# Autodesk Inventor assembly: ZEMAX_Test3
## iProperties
Created: 2005-04
Part Number: ZEMAX_Test3
Document SubType Name: Assembly
Designer: Nordmeyer
Manufacturer: Standard
Standards Organization: Custom
Author: Nordmeyer
